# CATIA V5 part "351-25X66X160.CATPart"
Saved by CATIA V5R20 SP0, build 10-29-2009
Part number: 351-25X66X160
Definition: NONE
Nomenclature: 351-25X66X160
Source: Unknown
Description: 351-25X66X160
Bounding box of the stored display mesh (mm): x -7 to 153, y -19 to 19, z -19 to 19
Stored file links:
  C:\Users\Utente\Desktop\IO LAVORO\3D X SITO CF\X SITO\PLASTICA\351\351-25X66X160.CATPart
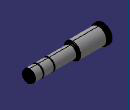
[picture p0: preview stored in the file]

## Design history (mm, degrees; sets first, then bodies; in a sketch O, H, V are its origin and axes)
Body1 "351-25X66X160" (main body)
  Solid1: solid without history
